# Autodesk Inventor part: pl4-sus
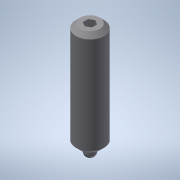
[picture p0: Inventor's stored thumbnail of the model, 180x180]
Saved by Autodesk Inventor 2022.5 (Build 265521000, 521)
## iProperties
Created: 2016-12
Part Number: pl4-sus
Material: 一般
Document SubType Name: Modeling
Designer: imaocorp
Density: 1 g/cm^3
Appearance: 既定
Author: imaocorp
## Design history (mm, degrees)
node "pl4-sus.x_t1"
node "pl4-sus"
node "Base1"
